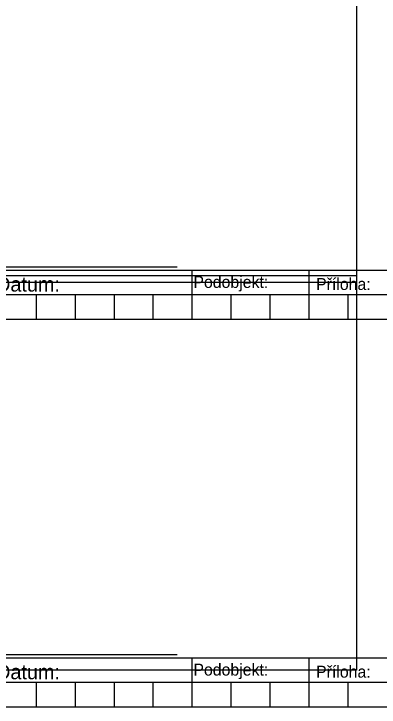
# Model space of a CAD drawing. Extents: x 1391 to 5528, y -6194 to 565.
# Drawn here: x 4185 to 4555, y -2428 to -1725 of the extents above; entities that cross this region are included whole.
import ezdxf

# ---------------------------------------------------------------- set-up
doc = ezdxf.new("R2010")
doc.units = 0
for name, color, linetype in [('Vrstva 2', 7, 'Continuous'), ('Vrstva 3', 7, 'Continuous'), ('Vrstva 8', 7, 'Continuous')]:
    doc.layers.add(name, color=color, linetype=linetype)

# ---------------------------------------------------------------- blocks, each defined once
blk = doc.blocks.new('_U1')
at = {"layer": 'Vrstva 8'}
for p, q in [((3.35, 0.25), (3.35, -0.25)), ((4.535, 0.25), (4.535, -0.25)), ((8.5, 0), (-8.5, 0)), ((1.77, 0), (1.77, -0.25)), ((2.165, 0), (2.165, -0.25)), ((2.56, 0), (2.56, -0.25)), ((2.955, 0), (2.955, -0.25)), ((3.745, 0), (3.745, -0.25)), ((4.14, 0), (4.14, -0.25)), ((4.93, 0), (4.93, -0.25))]:
    blk.add_line(p, q, dxfattribs=at)
blk.add_lwpolyline([(-8.5, 0.25), (8.5, 0.25), (8.5, -0.25), (-8.5, -0.25)], close=True, dxfattribs=at)
for s, p in [('Podobjekt:', (3.3643, 0.0699)), ('Příloha:', (4.6073, 0.0493))]:
    blk.add_text(s, height=0.12, dxfattribs=at).set_placement(p)
blk = doc.blocks.new('_U2')
at = {"layer": 'Vrstva 3'}
blk.add_line((-2.6675, -1.82505), (2.6675, -1.82505), dxfattribs=at)
for s, p in [('Razítko oprávněné osoby:', (-2.5675, 1.92495)), ('Podpis:', (-2.5675, -2.07505)), ('Datum:', (0.8325, -2.07505))]:
    blk.add_text(s, height=0.15, dxfattribs=at).set_placement(p)
blk = doc.blocks.new('_U3')
at = {"layer": 'Vrstva 2'}
blk.add_lwpolyline([(-5.33255, 2.00005), (5.33245, 2.00005), (5.33245, -1.99995), (-5.33255, -1.99995)], close=True, dxfattribs=at)

msp = doc.modelspace()

# ---------------------------------------------------------------- block references
at = {"layer": 'Vrstva 2', "xscale": 100, "yscale": 100}
for p in [(3998.89, -1797.75), (3998.89, -2190.81)]:
    msp.add_blockref('_U3', p, dxfattribs=at)
at = {"layer": 'Vrstva 3', "xscale": 100, "yscale": 100}
for p in [(4083.89, -1799.5), (4083.89, -2192.56)]:
    msp.add_blockref('_U2', p, dxfattribs=at)
at = {"layer": 'Vrstva 8', "xscale": 100, "yscale": 100}
for p in [(4030.56, -2010.25), (4030.56, -2403.31)]:
    msp.add_blockref('_U1', p, dxfattribs=at)

doc.saveas('drawing.dxf')
